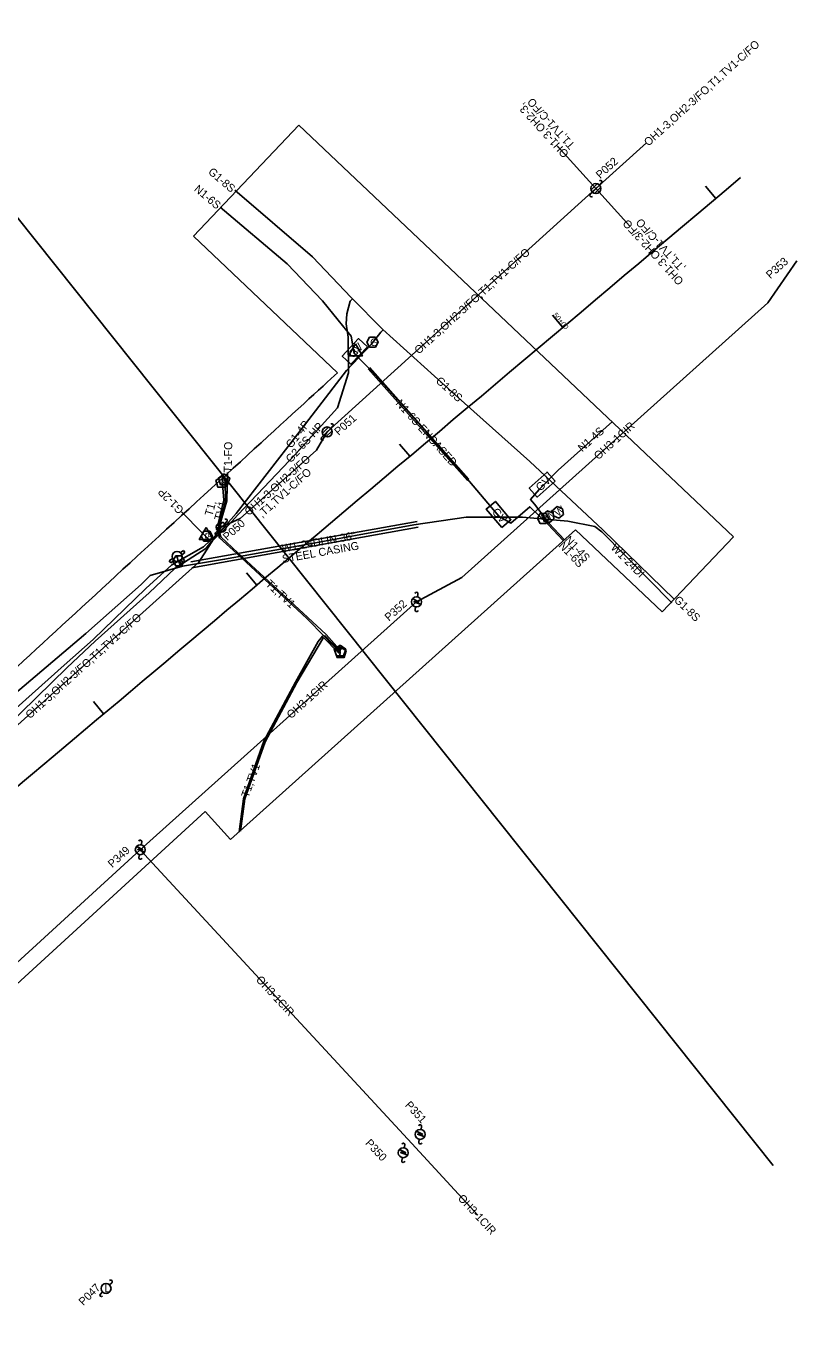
# Model space of a CAD drawing. Extents: x 1991878 to 2008544, y 770238 to 1141211.
# Drawn here: x 2006961 to 2007343, y 1140559 to 1141211 of the extents above; entities that cross this region are included whole.
import ezdxf

# ---------------------------------------------------------------- set-up
doc = ezdxf.new("R2010")
doc.units = 0
for name, color, linetype in [('RD_EX_SU_Gas', 7, 'Continuous'), ('RD_EX_SU_H2O', 7, 'Continuous'), ('RD_EX_SU_Misc', 7, 'Continuous'), ('RD_EX_SU_Ovhd', 7, 'Continuous'), ('RD_EX_SU_Pole', 7, 'Continuous'), ('RD_EX_SU_SwpLmt', 7, 'Continuous'), ('RD_EX_SU_Telecom', 7, 'Continuous'), ('RD_EX_SU_TX_Gas', 7, 'Continuous'), ('RD_EX_SU_TX_H2O', 7, 'Continuous'), ('RD_EX_SU_TX_Ovhd', 7, 'Continuous'), ('RD_EX_SU_TX_Pole', 7, 'Continuous'), ('RD_EX_SU_TX_Telecom', 7, 'Continuous'), ('RD_HC_Cl', 7, 'Continuous')]:
    doc.layers.add(name, color=color, linetype=linetype)

msp = doc.modelspace()

# ---------------------------------------------------------------- linework, layer by layer
at = {"layer": 'RD_EX_SU_Gas'}
for p, q in [((2007181.33, 1140983.47), (2007131.77, 1141039.32)), ((2007182.08, 1140984.13), (2007132.51, 1141039.99))]:
    msp.add_line(p, q, dxfattribs=at)
for points in [[(2007065.06, 1141128.59), (2007103.9, 1141095.28), (2007123.28, 1141075.02), (2007139.09, 1141059.04), (2007175.3, 1141026.41), (2007212.5, 1140993.04), (2007249.06, 1140958.9), (2007284.84, 1140924.1)], [(2007057.74, 1141120.16), (2007091.34, 1141091.83), (2007108.94, 1141073.31), (2007116.67, 1141063.63), (2007123.27, 1141055.63), (2007124.77, 1141047), (2007133.81, 1141038), (2007160.93, 1141007.68), (2007182.44, 1140982.95), (2007197.02, 1140965.71), (2007203.11, 1140962.26), (2007212.48, 1140970.43), (2007221.45, 1140961.64), (2007229.28, 1140953.37)], [(2006950.43, 1140859.88), (2006981.33, 1140890.04), (2006995.34, 1140903.14), (2007022.23, 1140927.41), (2007035.27, 1140939.68), (2007050.67, 1140949.55), (2007053.22, 1140952.93), (2007060.24, 1140959.27), (2007066.69, 1140966.32), (2007095.52, 1140996.83), (2007116.4, 1141019.79), (2007121.87, 1141037.4), (2007121.76, 1141055.12), (2007120.76, 1141061.85), (2007121.03, 1141066.8), (2007122.78, 1141073.18), (2007123.96, 1141074.31)], [(2006873.5, 1140738.51), (2006901.73, 1140761.75), (2006903.56, 1140763.42), (2006895.31, 1140772.28), (2006881.72, 1140785.43), (2006876.81, 1140792.08), (2006877.46, 1140794.49), (2006912.15, 1140827.15), (2006947.89, 1140862.5), (2006979.76, 1140891.26), (2006994.33, 1140904.09), (2007020.55, 1140929.45), (2007033.7, 1140941.3), (2007049.4, 1140950.39), (2007052.71, 1140953.47), (2007059.51, 1140959.79), (2007065.74, 1140966.97), (2007091.55, 1141000.3), (2007120.95, 1141038.48), (2007133.17, 1141051.57), (2007138.1, 1141057.67), (2007139.29, 1141058.85)], [(2007229.81, 1140953.78), (2007222.07, 1140962.11), (2007214.79, 1140971.73), (2007212.9, 1140974.02), (2007217.24, 1140979.02), (2007226.76, 1140988.76), (2007253.88, 1141012.95)], [(2007052.7, 1140953.47), (2007052, 1140954.22), (2007048.79, 1140957.31), (2007038.43, 1140967.9)]]:
    msp.add_lwpolyline(points, dxfattribs=at)
for points in [[(2007131.34, 1141050.39), (2007123.15, 1141041.62), (2007118.76, 1141045.71), (2007126.95, 1141054.48)], [(2007135.35, 1141050.12), (2007136.79, 1141052.62), (2007135.35, 1141055.12), (2007132.46, 1141055.12), (2007131.02, 1141052.62), (2007132.46, 1141050.12)], [(2007225.18, 1140983.26), (2007216.25, 1140975.25), (2007212.24, 1140979.71), (2007221.17, 1140987.73)], [(2007198.51, 1140960.02), (2007190.76, 1140969.19), (2007195.34, 1140973.06), (2007203.09, 1140963.9)], [(2007052.54, 1140953.14), (2007053.99, 1140955.64), (2007052.54, 1140958.14), (2007049.66, 1140958.14), (2007048.21, 1140955.64), (2007049.66, 1140953.14)]]:
    msp.add_lwpolyline(points, close=True, dxfattribs=at)
at = {"layer": 'RD_EX_SU_H2O'}
for p, q in [((2007156.27, 1140963.08), (2007043.06, 1140942.89)), ((2007156.8, 1140960.13), (2007043.58, 1140939.93)), ((2007039.45, 1140948.59), (2007037.91, 1140947.45)), ((2007038.62, 1140946.41), (2007040.2, 1140947.58)), ((2007040.2, 1140947.58), (2007039.45, 1140948.59)), ((2007033.95, 1140944.52), (2007032.36, 1140943.34)), ((2007032.36, 1140943.34), (2007033.11, 1140942.33)), ((2007033.11, 1140942.33), (2007034.74, 1140943.54)), ((2007037.15, 1140943.2), (2007038.12, 1140941.89)), ((2007038.12, 1140941.89), (2007039.13, 1140942.64)), ((2007039.13, 1140942.64), (2007038.17, 1140943.93))]:
    msp.add_line(p, q, dxfattribs=at)
for points in [[(2006705.8, 1140653.82), (2006721.81, 1140666.7), (2006726.48, 1140670.22), (2006749.2, 1140688.87), (2006760.06, 1140698.18), (2006801.94, 1140731.48), (2006837.34, 1140761.88), (2006872.75, 1140798.11), (2006888.92, 1140812.96), (2006908.58, 1140833.31), (2006943.2, 1140866.93), (2006990.62, 1140906.95), (2007018.28, 1140931.47), (2007022.75, 1140936), (2007039, 1140940.71), (2007059.99, 1140944.12), (2007094.46, 1140950.28), (2007154.59, 1140961.32), (2007180.73, 1140965.17), (2007208.8, 1140965.18), (2007231.59, 1140963.11), (2007245.06, 1140960.58), (2007248.47, 1140957.93), (2007283.51, 1140922.44)], [(2007038.75, 1140940.64), (2007038.56, 1140941.29), (2007036.69, 1140943.75), (2007036.47, 1140944.83), (2007036.25, 1140945.56)]]:
    msp.add_lwpolyline(points, dxfattribs=at)
for points in [[(2007222.11, 1140964.5), (2007220.66, 1140966.99), (2007217.78, 1140966.99), (2007216.33, 1140964.5), (2007217.78, 1140962), (2007220.66, 1140962)], [(2007224.13, 1140967.24), (2007221.44, 1140968.29), (2007219.18, 1140966.49), (2007219.61, 1140963.64), (2007222.3, 1140962.58), (2007224.56, 1140964.38)], [(2007228.9, 1140969.38), (2007226.22, 1140970.44), (2007223.96, 1140968.64), (2007224.39, 1140965.78), (2007227.08, 1140964.73), (2007229.33, 1140966.53)], [(2007039.91, 1140943.32), (2007038.46, 1140945.82), (2007035.58, 1140945.82), (2007034.13, 1140943.32), (2007035.58, 1140940.82), (2007038.46, 1140940.82)]]:
    msp.add_lwpolyline(points, close=True, dxfattribs=at)
for radius in [2.52, 0.315]:
    msp.add_circle((2007036.25, 1140945.56), radius, dxfattribs=at)
for start, end in [(19.85724, 48.83356), (204.20353, 233.17985), (290.76407, 319.73131)]:
    msp.add_arc((2007036.25, 1140945.56), 2.52, start, end, dxfattribs=at)
at = {"layer": 'RD_EX_SU_Misc'}
for points in [[(2007125.37, 1141051.83), (2007121.9, 1141045.83), (2007128.83, 1141045.83)], [(2007050.79, 1140960.08), (2007047.33, 1140954.08), (2007054.26, 1140954.08)]]:
    msp.add_lwpolyline(points, close=True, dxfattribs=at)
at = {"layer": 'RD_EX_SU_Ovhd'}
for p, q in [((2007245.57, 1141129.46), (2007226.32, 1141150.71)), ((2007245.57, 1141129.46), (2007270.79, 1141152.32)), ((2007111.26, 1141007.77), (2007245.57, 1141129.46)), ((2007262.59, 1141110.67), (2007245.57, 1141129.46)), ((2007155.91, 1140922.81), (2007017.86, 1140798.94)), ((2007017.86, 1140798.94), (2006870.01, 1140663.43)), ((2007017.86, 1140798.94), (2007153.52, 1140652.02)), ((2007153.52, 1140652.02), (2007186.59, 1140616.21))]:
    msp.add_line(p, q, dxfattribs=at)
for points in [[(2007346.03, 1141093.41), (2007331.41, 1141072.26), (2007178.51, 1140935.06), (2007155.91, 1140922.81)], [(2007058.3, 1140960.14), (2007067.83, 1140964.5), (2007105.92, 1140998.76), (2007111.26, 1141007.77)], [(2006914.95, 1140831.38), (2006933.52, 1140840.64), (2007047.11, 1140942.67), (2007058.3, 1140960.14)]]:
    msp.add_lwpolyline(points, dxfattribs=at)
at = {"layer": 'RD_EX_SU_Pole'}
for p, q in [((2007243.15, 1141128.82), (2007246.21, 1141131.88)), ((2007243.8, 1141127.69), (2007247.33, 1141131.23)), ((2007244.92, 1141127.05), (2007247.98, 1141130.11)), ((2007247.33, 1141131.23), (2007248.39, 1141132.29)), ((2007242.74, 1141126.63), (2007243.8, 1141127.69)), ((2007108.43, 1141004.94), (2007109.49, 1141006)), ((2007108.85, 1141007.12), (2007111.91, 1141010.18)), ((2007109.49, 1141006), (2007113.03, 1141009.54)), ((2007110.61, 1141005.36), (2007113.68, 1141008.42)), ((2007113.03, 1141009.54), (2007114.09, 1141010.6)), ((2007055.88, 1140959.49), (2007058.95, 1140962.55)), ((2007056.53, 1140958.37), (2007060.07, 1140961.91)), ((2007057.65, 1140957.72), (2007060.71, 1140960.79)), ((2007060.07, 1140961.91), (2007061.13, 1140962.97)), ((2007055.47, 1140957.31), (2007056.53, 1140958.37)), ((2007156.36, 1140925.27), (2007156.63, 1140926.75)), ((2007155.2, 1140918.88), (2007155.46, 1140920.35)), ((2007018.3, 1140801.4), (2007018.57, 1140802.88)), ((2007017.14, 1140795.01), (2007017.41, 1140796.48)), ((2007158.19, 1140659.09), (2007158.45, 1140660.57)), ((2007157.02, 1140652.69), (2007157.29, 1140654.17)), ((2007149.72, 1140649.91), (2007149.99, 1140651.38)), ((2007148.56, 1140643.51), (2007148.83, 1140644.99)), ((2007002.51, 1140581.38), (2007003.57, 1140582.44)), ((2006997.92, 1140576.78), (2006998.98, 1140577.84))]:
    msp.add_line(p, q, dxfattribs=at)
for points in [[(2007154.44, 1140924.24), (2007156.27, 1140923.05), (2007154.61, 1140922.88), (2007157.68, 1140921.75), (2007157.68, 1140921.75), (2007155.5, 1140922.79), (2007157.1, 1140922.91)], [(2007016.39, 1140800.37), (2007018.21, 1140799.19), (2007016.56, 1140799.02), (2007019.63, 1140797.88), (2007019.63, 1140797.88), (2007017.45, 1140798.92), (2007019.04, 1140799.05)], [(2007156.27, 1140658.06), (2007158.1, 1140656.87), (2007156.44, 1140656.7), (2007159.51, 1140655.56), (2007159.51, 1140655.56), (2007157.33, 1140656.6), (2007158.92, 1140656.73)], [(2007147.81, 1140648.87), (2007149.63, 1140647.69), (2007147.98, 1140647.52), (2007151.05, 1140646.38), (2007151.05, 1140646.38), (2007148.87, 1140647.42), (2007150.46, 1140647.55)]]:
    msp.add_lwpolyline(points, close=True, dxfattribs=at)
for centre in [(2007245.57, 1141129.46), (2007111.26, 1141007.77), (2007058.3, 1140960.14), (2007155.91, 1140922.81), (2007017.86, 1140798.94), (2007157.74, 1140656.63), (2007149.27, 1140647.45), (2007000.74, 1140579.61)]:
    msp.add_circle(centre, 2.5, dxfattribs=at)
for centre, start, end in [((2007247.86, 1141132.82), 315.01158, 135.01158), ((2007243.27, 1141126.1), 135.01158, 315.01158), ((2007113.56, 1141011.13), 315.01158, 135.01158), ((2007108.96, 1141004.41), 135.01158, 315.01158), ((2007060.6, 1140963.5), 315.01158, 135.01158), ((2007056, 1140956.78), 135.01158, 315.01158), ((2007155.89, 1140926.88), 349.68899, 169.68899), ((2007155.93, 1140918.74), 169.68899, 349.68899), ((2007017.83, 1140803.01), 349.68899, 169.68899), ((2007017.88, 1140794.87), 169.68899, 349.68899), ((2007157.72, 1140660.7), 349.68899, 169.68899), ((2007149.25, 1140651.52), 349.68899, 169.68899), ((2007157.76, 1140652.56), 169.68899, 349.68899), ((2007149.3, 1140643.38), 169.68899, 349.68899), ((2007003.04, 1140582.97), 315.01158, 135.01158), ((2006998.45, 1140576.25), 135.01158, 315.01158)]:
    msp.add_arc(centre, 0.75, start, end, dxfattribs=at)
at = {"layer": 'RD_EX_SU_SwpLmt'}
for p, q in [((2007044.48, 1141105.62), (2007097.03, 1141161.1)), ((2007097.03, 1141161.1), (2007314.29, 1140955.31)), ((2007116.49, 1141037.4), (2007044.48, 1141105.62)), ((2007062.88, 1140804), (2007235.43, 1140958.81)), ((2007235.43, 1140958.81), (2007278.74, 1140917.78)), ((2007278.74, 1140917.78), (2007314.29, 1140955.31)), ((2006847.85, 1140632.58), (2007050.24, 1140818.09)), ((2007050.24, 1140818.09), (2007062.88, 1140804))]:
    msp.add_line(p, q, dxfattribs=at)
msp.add_open_spline([(2006800.95, 1140750.58), (2006833.15, 1140777.89), (2006915.9, 1140852.93), (2007008.95, 1140939.06), (2007100.54, 1141022.84), (2007116.49, 1141037.4)], degree=3, dxfattribs=at)
at = {"layer": 'RD_EX_SU_Telecom'}
for points in [[(2007058.43, 1140985.57), (2007055.58, 1140983.5), (2007056.67, 1140980.14), (2007060.2, 1140980.14), (2007061.29, 1140983.5)], [(2007059.76, 1140986.79), (2007056.9, 1140984.71), (2007057.99, 1140981.36), (2007061.52, 1140981.36), (2007062.61, 1140984.71)], [(2007117.69, 1140901.22), (2007114.83, 1140899.14), (2007115.92, 1140895.79), (2007119.45, 1140895.79), (2007120.54, 1140899.14)], [(2007117.97, 1140900.43), (2007115.11, 1140898.36), (2007116.2, 1140895), (2007119.73, 1140895), (2007120.82, 1140898.36)]]:
    msp.add_lwpolyline(points, close=True, dxfattribs=at)
for points in [[(2007061.44, 1140987.52), (2007061.14, 1140973.31), (2007057.83, 1140961.98), (2007058.3, 1140960.14)], [(2007058.43, 1140982.57), (2007059.01, 1140981.93), (2007059.57, 1140973.74), (2007056.68, 1140961.12), (2007058.3, 1140960.14)], [(2007059.76, 1140983.79), (2007060.26, 1140983.18), (2007060.41, 1140973.5), (2007057.43, 1140961.35), (2007058.3, 1140960.14)], [(2007058.3, 1140960.14), (2007056.1, 1140959.49), (2007057.42, 1140954.79), (2007066.1, 1140947), (2007101.12, 1140914.59), (2007109.99, 1140905.45), (2007117.05, 1140898.03), (2007117.97, 1140897.43)], [(2007058.3, 1140960.14), (2007056.73, 1140959.56), (2007058.04, 1140955.31), (2007066.57, 1140947.41), (2007101.62, 1140914.98), (2007110.71, 1140906.47), (2007117.38, 1140899.07), (2007117.69, 1140898.22)], [(2007117.69, 1140898.22), (2007116.92, 1140898.94), (2007110.21, 1140905.94), (2007108.92, 1140905.66), (2007106.76, 1140903.06), (2007095.38, 1140882.65), (2007079.63, 1140853.28), (2007069.38, 1140824.4), (2007067.31, 1140807.94)], [(2007117.97, 1140897.43), (2007116.76, 1140897.58), (2007109.47, 1140904.97), (2007096.09, 1140882.5), (2007080.3, 1140852.85), (2007070.14, 1140824.44), (2007067.93, 1140808.26)]]:
    msp.add_lwpolyline(points, dxfattribs=at)
at = {"layer": 'RD_HC_Cl'}
for p, q in [((2006879.86, 1141210.69), (2007334.1, 1140641.09)), ((2007300.36, 1141130.66), (2007305.51, 1141124.54)), ((2007223.92, 1141066.18), (2007229.08, 1141060.06)), ((2007147.46, 1141001.74), (2007152.61, 1140995.62)), ((2007070.96, 1140937.34), (2007076.11, 1140931.22)), ((2006994.41, 1140873.02), (2006999.55, 1140866.89))]:
    msp.add_line(p, q, dxfattribs=at)
msp.add_open_spline([(2005275.25, 1139802.58), (2005417.33, 1139911.24), (2005548.93, 1140008.55), (2005664.1, 1140090.03), (2005747, 1140153.49), (2005819.82, 1140205.85), (2005880.88, 1140246.35), (2005986.62, 1140308.11), (2006024.68, 1140326.82), (2006100.51, 1140359.48), (2006273.91, 1140424.96), (2006364.15, 1140455.15), (2006461.52, 1140489.97), (2006524.81, 1140519.99), (2006584.45, 1140553.16), (2006699.96, 1140622.09), (2006754.11, 1140664.4), (2006830.67, 1140723.8), (2007317.85, 1141134.95)], degree=2, dxfattribs=at)

# ---------------------------------------------------------------- texts
at = {"layer": 'RD_EX_SU_Gas'}
for rotation, p in [(46.95347, (2007124.34, 1141044.36)), (41.90204, (2007217.68, 1140977.87)), (310.21819, (2007193.34, 1140967.68))]:
    msp.add_text('GV', height=4, rotation=rotation, dxfattribs=at).set_placement(p)
for p in [(2007132.75, 1141050.75), (2007049.95, 1140953.76)]:
    msp.add_text('G', height=3.75, dxfattribs=at).set_placement(p)
at = {"layer": 'RD_EX_SU_H2O'}
for p in [(2007218.01, 1140962.62), (2007035.81, 1140941.45)]:
    msp.add_text('V', height=3.75, dxfattribs=at).set_placement(p)
for p in [(2007221.95, 1140963.1), (2007226.73, 1140965.25)]:
    msp.add_text('W', height=3.75, rotation=38.57195, dxfattribs=at).set_placement(p)
at = {"layer": 'RD_EX_SU_Misc'}
for p in [(2007124.61, 1141046.63), (2007050.04, 1140954.88)]:
    msp.add_text('U', height=2.4, dxfattribs=at).set_placement(p)
at = {"layer": 'RD_EX_SU_Pole'}
msp.add_text('L', height=4, rotation=0.01158, dxfattribs=at).set_placement((2006999.93, 1140577.68))
at = {"layer": 'RD_EX_SU_Telecom'}
for s, height, p in [('C', 4, (2007058.53, 1140981.79)), ('T', 3.75, (2007057.2, 1140980.34)), ('T', 3.75, (2007116.46, 1140895.99)), ('C', 4, (2007116.74, 1140895.43))]:
    msp.add_text(s, height=height, dxfattribs=at).set_placement(p)
at = {"layer": 'RD_EX_SU_TX_Gas'}
for s, rotation, p in [('G1-8S', 319.38336, (2007051.46, 1141137.27)), ('N1-6S', 319.85749, (2007044.42, 1141128.65)), ('G1-8S', 317.97267, (2007165.19, 1141032.83)), ('N1-6S ENCASED', 311.81936, (2007145.26, 1141021.85)), ('G1-4P', 52.40433, (2007093.33, 1140999.29)), ('G2-6S-HP', 47.72617, (2007093.08, 1140992.05)), ('N1-4S', 41.72404, (2007238.71, 1140997.59)), ('G1-2P', 134.37925, (2007039.94, 1140969.12)), ('N1-6S', 313.45913, (2007226.64, 1140950.68)), ('N1-4S', 313.45913, (2007229.68, 1140953.52)), ('G1-8S', 315.79221, (2007284.28, 1140923.39))]:
    msp.add_text(s, height=4, rotation=rotation, dxfattribs=at).set_placement(p)
at = {"layer": 'RD_EX_SU_TX_H2O'}
for s, rotation, p in [('W1-24DI IN 36"', 10.13612, (2007088.95, 1140947.54)), ('STEEL CASING', 10.13612, (2007089.11, 1140942.28)), ('W1-24DI', 314.63692, (2007252.67, 1140949.58))]:
    msp.add_text(s, height=4, rotation=rotation, dxfattribs=at).set_placement(p)
at = {"layer": 'RD_EX_SU_TX_Ovhd'}
for s, rotation, p in [('OH1-3,OH2-3/FO,T1,TV1-C/FO', 42.17955, (2007271.79, 1141150.39)), ('T1,TV1-C/FO', 132.17955, (2007235.38, 1141151.39)), ('OH1-3,OH2-3,', 132.17955, (2007232.3, 1141147.03)), ('OH1-3,OH2-3/FO', 132.17955, (2007289.68, 1141083.39)), (',T1,TV1-C/FO', 132.17955, (2007290.66, 1141090.06)), ('OH1-3,OH2-3/FO,T1,TV1-C/FO', 42.17955, (2007157.05, 1141046.41)), ('OH3-1CIR', 41.90204, (2007246.76, 1140993.62)), ('OH1-3,OH2-3/FO', 41.96641, (2007072.13, 1140965.68)), (',T1,TV1-C/FO', 41.96641, (2007078.8, 1140964.68)), ('OH1-3,OH2-3/FO,T1,TV1-C/FO', 41.93162, (2006962.68, 1140864.15)), ('OH3-1CIR', 41.89943, (2007093.22, 1140864.15)), ('OH3-1CIR', 312.71921, (2007075.38, 1140733.7)), ('OH3-1CIR', 312.71921, (2007176.28, 1140624.43))]:
    msp.add_text(s, height=4, rotation=rotation, dxfattribs=at).set_placement(p)
at = {"layer": 'RD_EX_SU_TX_Pole'}
for s, rotation, p in [('P052', 42.17955, (2007247.73, 1141134.11)), ('P353', 41.90204, (2007332.74, 1141084.14)), ('P051', 42.17955, (2007117.04, 1141005.77)), ('P050', 41.96641, (2007061.34, 1140953.15)), ('P352', 41.89943, (2007142.15, 1140912.94)), ('P349', 42.50913, (2007003.86, 1140789.67)), ('P351', 312.71921, (2007149.9, 1140671.02)), ('P350', 312.71921, (2007130.03, 1140652.02)), ('P047', 45.01158, (2006989.45, 1140570.75))]:
    msp.add_text(s, height=4, rotation=rotation, dxfattribs=at).set_placement(p)
at = {"layer": 'RD_EX_SU_TX_Telecom'}
for s, rotation, p in [('T1-FO', 88.77917, (2007063.51, 1140987.44)), ('T1,', 74.33029, (2007053.8, 1140965.45)), ('TV1', 74.33029, (2007058.56, 1140963.13)), ('T1,TV1', 317.21282, (2007080.17, 1140931.32)), ('T1,TV1', 70.31624, (2007071.93, 1140824.69))]:
    msp.add_text(s, height=4, rotation=rotation, dxfattribs=at).set_placement(p)
at = {"layer": 'RD_HC_Cl'}
msp.add_text('50+00', height=2.5, rotation=310.12388, dxfattribs=at).set_placement((2007223.97, 1141066.13))

doc.saveas('drawing.dxf')
